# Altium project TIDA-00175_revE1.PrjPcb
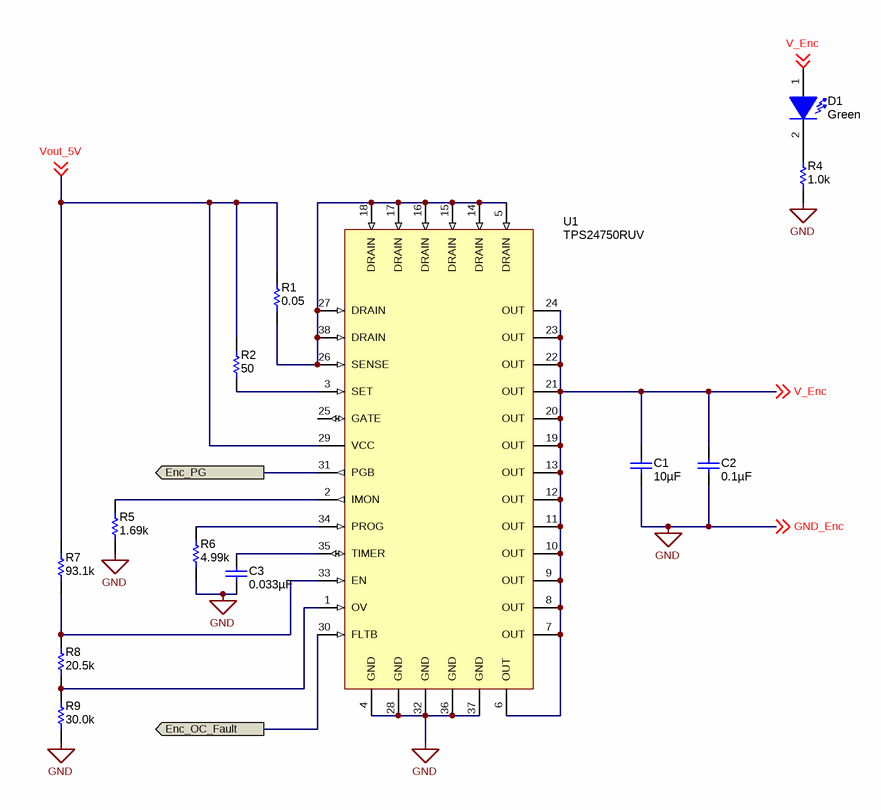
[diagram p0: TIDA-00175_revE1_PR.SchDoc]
CopyrightYear: 2014; PCB_Layout: Mogensen; PCB_Rev: E1; PRJ_Customer: Public Release; PRJ_Engineer: Mogensen/Staebler; PRJ_Number: TIDA-00175; PRJ_Title: Interface to an BiSS-C Position Encoder; SCH_Rev: E1; TechSupport: http://www.ti.com/support
4 sheets, 124 parts. Net scope: flat (ports and power ports of the same name join across sheets).
Board file: TIDA-00175_revE1_PCB.PcbDoc
Sheets:
  TIDA-00175_revE1_PR.SchDoc
  TIDA-00175_revE1_PS.SchDoc
  TIDA-00175_revE1_SC.SchDoc
  TIDA-00175_revE1_Block_Diagram.SchDoc

## Sheet TIDA-00175_revE1_PR.SchDoc
size 431 x 279 mm; Date: Not shown in title block; ApprovedBy: Not shown in title block; CheckedBy: Not shown in title block; Author: Not shown in title block; CompanyName: Not shown in title block; Engineer: Not shown in title block; Organization: Not shown in title block; Address1: Not shown in title block; Address2: Not shown in title block; Address3: Not shown in title block; Address4: Not shown in title block; DocumentNumber: 3; Revision: Use project parameter SCH_Rev; SheetNumber: 3; SheetTotal: 4; PageSetup: Record=PageOptions|CenterHorizontal=True|CenterVertical=True|PrintScale=0.62|XCorrection=1.00|YCorrection=1.00|PrintKind=0|BorderSize=5000000|LeftOffset=0|BottomOffset=0|Orientation=2|PaperLength=1000|PaperWidth=1000|Scale=100|PaperSource=15|PrintQuality=600|MediaType=1|DitherType=10|PaperKind=Letter|PrintScaleMode=1

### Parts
C1  ValueDisplayed: 10µF  [0805_HV]  (hidden comment: C2012X5R1E106K125AB)
C2  ValueDisplayed: 0.1µF  [0603]  (hidden comment: C1608X7R1E104K)
C3  ValueDisplayed: 0.033µF  [0603]  (hidden comment: GRM188R71H333KA61D)
D1  value Green  [LG L29K_GREEN]  (hidden comment: LG L29K-G2J1-24-Z)
R1  value 0.05  [0603]  (hidden comment: ERJ-L03KF50MV)
R2  value 50  [0603]  (hidden comment: CRCW060350R0FKEA)
R4  value 1.0k  [0603]  (hidden comment: CRCW06031K00JNEA)
R5  value 1.69k  [0603]  (hidden comment: CRCW06031K69FKEA)
R6  value 4.99k  [0603]  (hidden comment: CRCW06034K99FKEA)
R7  value 93.1k  [0603]  (hidden comment: CRCW060393K1FKEA)
R8  value 20.5k  [0603]  (hidden comment: CRCW060320K5FKEA)
R9  value 30.0k  [0603]  (hidden comment: RC0603FR-0730KL)
U1  TPS24750RUV  [RUV0036A]

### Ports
Enc_OC_Fault (out), Enc_PG (out)

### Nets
GND: C1.2 C2.2 C3.1 R4.1 R5.1 R6.1 R9.1 U1.4(GND) U1.28(GND) U1.32(GND) U1.36(GND) U1.37(GND) ; off-sheet GND_Enc  [also labelled GND_Enc]
Enc_OC_Fault: U1.30(FLTB) ; port Enc_OC_Fault
Enc_PG: U1.31(PGB) ; port Enc_PG
V_Enc: C1.1 C2.1 D1.1(A) U1.6(OUT) U1.7(OUT) U1.8(OUT) U1.9(OUT) U1.10(OUT) U1.11(OUT) U1.12(OUT) U1.13(OUT) U1.19(OUT) U1.20(OUT) U1.21(OUT) U1.22(OUT) U1.23(OUT) U1.24(OUT) ; off-sheet V_Enc
Vout_5V: R1.2 R2.2 R7.2 U1.29(VCC) ; off-sheet Vout_5V
NetC3_2: C3.2 U1.35(TIMER)
NetD1_2: D1.2(K) R4.2
NetR1_1: R1.1 U1.5(DRAIN) U1.14(DRAIN) U1.15(DRAIN) U1.16(DRAIN) U1.17(DRAIN) U1.18(DRAIN) U1.26(SENSE) U1.27(DRAIN) U1.38(DRAIN)
NetR2_1: R2.1 U1.3(SET)
NetR5_2: R5.2 U1.2(IMON)
NetR6_2: R6.2 U1.34(PROG)
NetR7_1: R7.1 R8.2 U1.33(EN)
NetR8_1: R8.1 R9.2 U1.1(OV)

Not connected (* = marked no-connect by the designer): U1 25(GATE)

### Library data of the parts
C1 = C2012X5R1E106K125AB: CAP, CERM, 10uF, 25V, +/-10%, X5R, 0805; Manufacturer: TDK; Polarized: N; CompType: Capacitor; U/M: EA; Cap_F: 0.00001; Tolerance_%: 10; Value1: Unknown; VDC_V: 25; TaMin_C: -55; TaMax_C: 85; Cap_Case: 0805
C2 = C1608X7R1E104K: CAP, CERM, 0.1uF, 25V, +/-10%, X7R, 0603; Manufacturer: TDK; Polarized: N; CompType: Capacitor; U/M: EA; Cap_F: 0.0000001; Tolerance_%: 10; ESR_Ohm: 0.017; Value1: 0.017 ohm; VDC_V: 25; TaMin_C: -55; TaMax_C: 125
C3 = GRM188R71H333KA61D: CAP, CERM, 0.033uF, 50V, +/-10%, X7R, 0603; Manufacturer: MuRata; Polarized: N; CompType: Capacitor; U/M: EA; Cap_F: 0.000000033; Tolerance_%: 10; Value1: Unknown; VDC_V: 50; TaMin_C: -55; TaMax_C: 125
D1 = LG L29K-G2J1-24-Z: LED, Green, SMD; Manufacturer: OSRAM; Vf_V: 1.7; Value2: 1.7V; Io_A: 0.002; Tjmax_C: 110; Value1: W; U/M: EA
R1 = ERJ-L03KF50MV: RES, 0.05 ohm, 1%, 0.1W, 0603; Manufacturer: Panasonic; CompType: Resistor; Value_Code: R050; Tolerance_%: 1; Power_W: 0.1; TempCo: 200 ppm/C; EIA_Code: E96; U/M: EA
R2 = CRCW060350R0FKEA: RES, 50 ohm, 1%, 0.1W, 0603; Manufacturer: Vishay-Dale; CompType: Resistor; Value_Code: 50R0; Tolerance_%: 1; Power_W: 0.1; VDC_V: 75; TempCo: 100 ppm/C; U/M: EA
R4 = CRCW06031K00JNEA: RES, 1.0k ohm, 5%, 0.1W, 0603; Manufacturer: Vishay-Dale; CompType: Resistor; Res_ohm: 1000; Value_Code: 1k00; Tolerance_%: 5; Power_W: 0.1; VDC_V: 75; TempCo: 200 ppm/C; EIA_Code: E24; U/M: EA
R5 = CRCW06031K69FKEA: RES, 1.69k ohm, 1%, 0.1W, 0603; Manufacturer: Vishay-Dale; CompType: Resistor; Res_ohm: 1690; Value_Code: 1k69; Tolerance_%: 1; Power_W: 0.1; VDC_V: 75; TempCo: 100 ppm/C; EIA_Code: E96; U/M: EA
R6 = CRCW06034K99FKEA: RES, 4.99k ohm, 1%, 0.1W, 0603; Manufacturer: Vishay-Dale; CompType: Resistor; Res_ohm: 4990; Value_Code: 4k99; Tolerance_%: 1; Power_W: 0.1; VDC_V: 75; TempCo: 100 ppm/C; EIA_Code: E96; U/M: EA
R7 = CRCW060393K1FKEA: RES, 93.1k ohm, 1%, 0.1W, 0603; Manufacturer: Vishay-Dale; CompType: Resistor; Res_ohm: 93100; Value_Code: 93k1; Tolerance_%: 1; Power_W: 0.1; VDC_V: 75; TempCo: 100 ppm/C; EIA_Code: E96; U/M: EA
R8 = CRCW060320K5FKEA: RES, 20.5k ohm, 1%, 0.1W, 0603; Manufacturer: Vishay-Dale; CompType: Resistor; Res_ohm: 20500; Value_Code: 20k5; Tolerance_%: 1; Power_W: 0.1; VDC_V: 75; TempCo: 100 ppm/C; EIA_Code: E96; U/M: EA
R9 = RC0603FR-0730KL: RES, 30.0k ohm, 1%, 0.1W, 0603; Manufacturer: Yageo America; CompType: Resistor; Res_ohm: 30000; Value_Code: 30k0; Tolerance_%: 1; Power_W: 0.1; VDC_V: 150; TempCo: 200 ppm/C; U/M: EA
U1 = TPS24750RUV: 2.5 to 18 V Positive Voltage 10A Integrated Hot-Swap Controller, RUV0036A; Alternate Manufacturer: None; Manufacturer: Texas Instruments; SymbolCreator: a0411947; CompType: IC; U/M: EA

## Sheet TIDA-00175_revE1_PS.SchDoc
size 431 x 279 mm; Date: Not shown in title block; ApprovedBy: Not shown in title block; CheckedBy: Not shown in title block; Author: Not shown in title block; CompanyName: Not shown in title block; Engineer: Not shown in title block; Organization: Not shown in title block; Address1: Not shown in title block; Address2: Not shown in title block; Address3: Not shown in title block; Address4: Not shown in title block; DocumentNumber: 2; Revision: Use project parameter SCH_Rev; SheetNumber: 2; SheetTotal: 4; PageSetup: Record=PageOptions|CenterHorizontal=True|CenterVertical=True|PrintScale=0.62|XCorrection=1.00|YCorrection=1.00|PrintKind=0|BorderSize=5000000|LeftOffset=0|BottomOffset=0|Orientation=2|PaperLength=1000|PaperWidth=1000|Scale=100|PaperSource=15|PrintQuality=600|MediaType=1|DitherType=10|PaperKind=Letter|PrintScaleMode=1
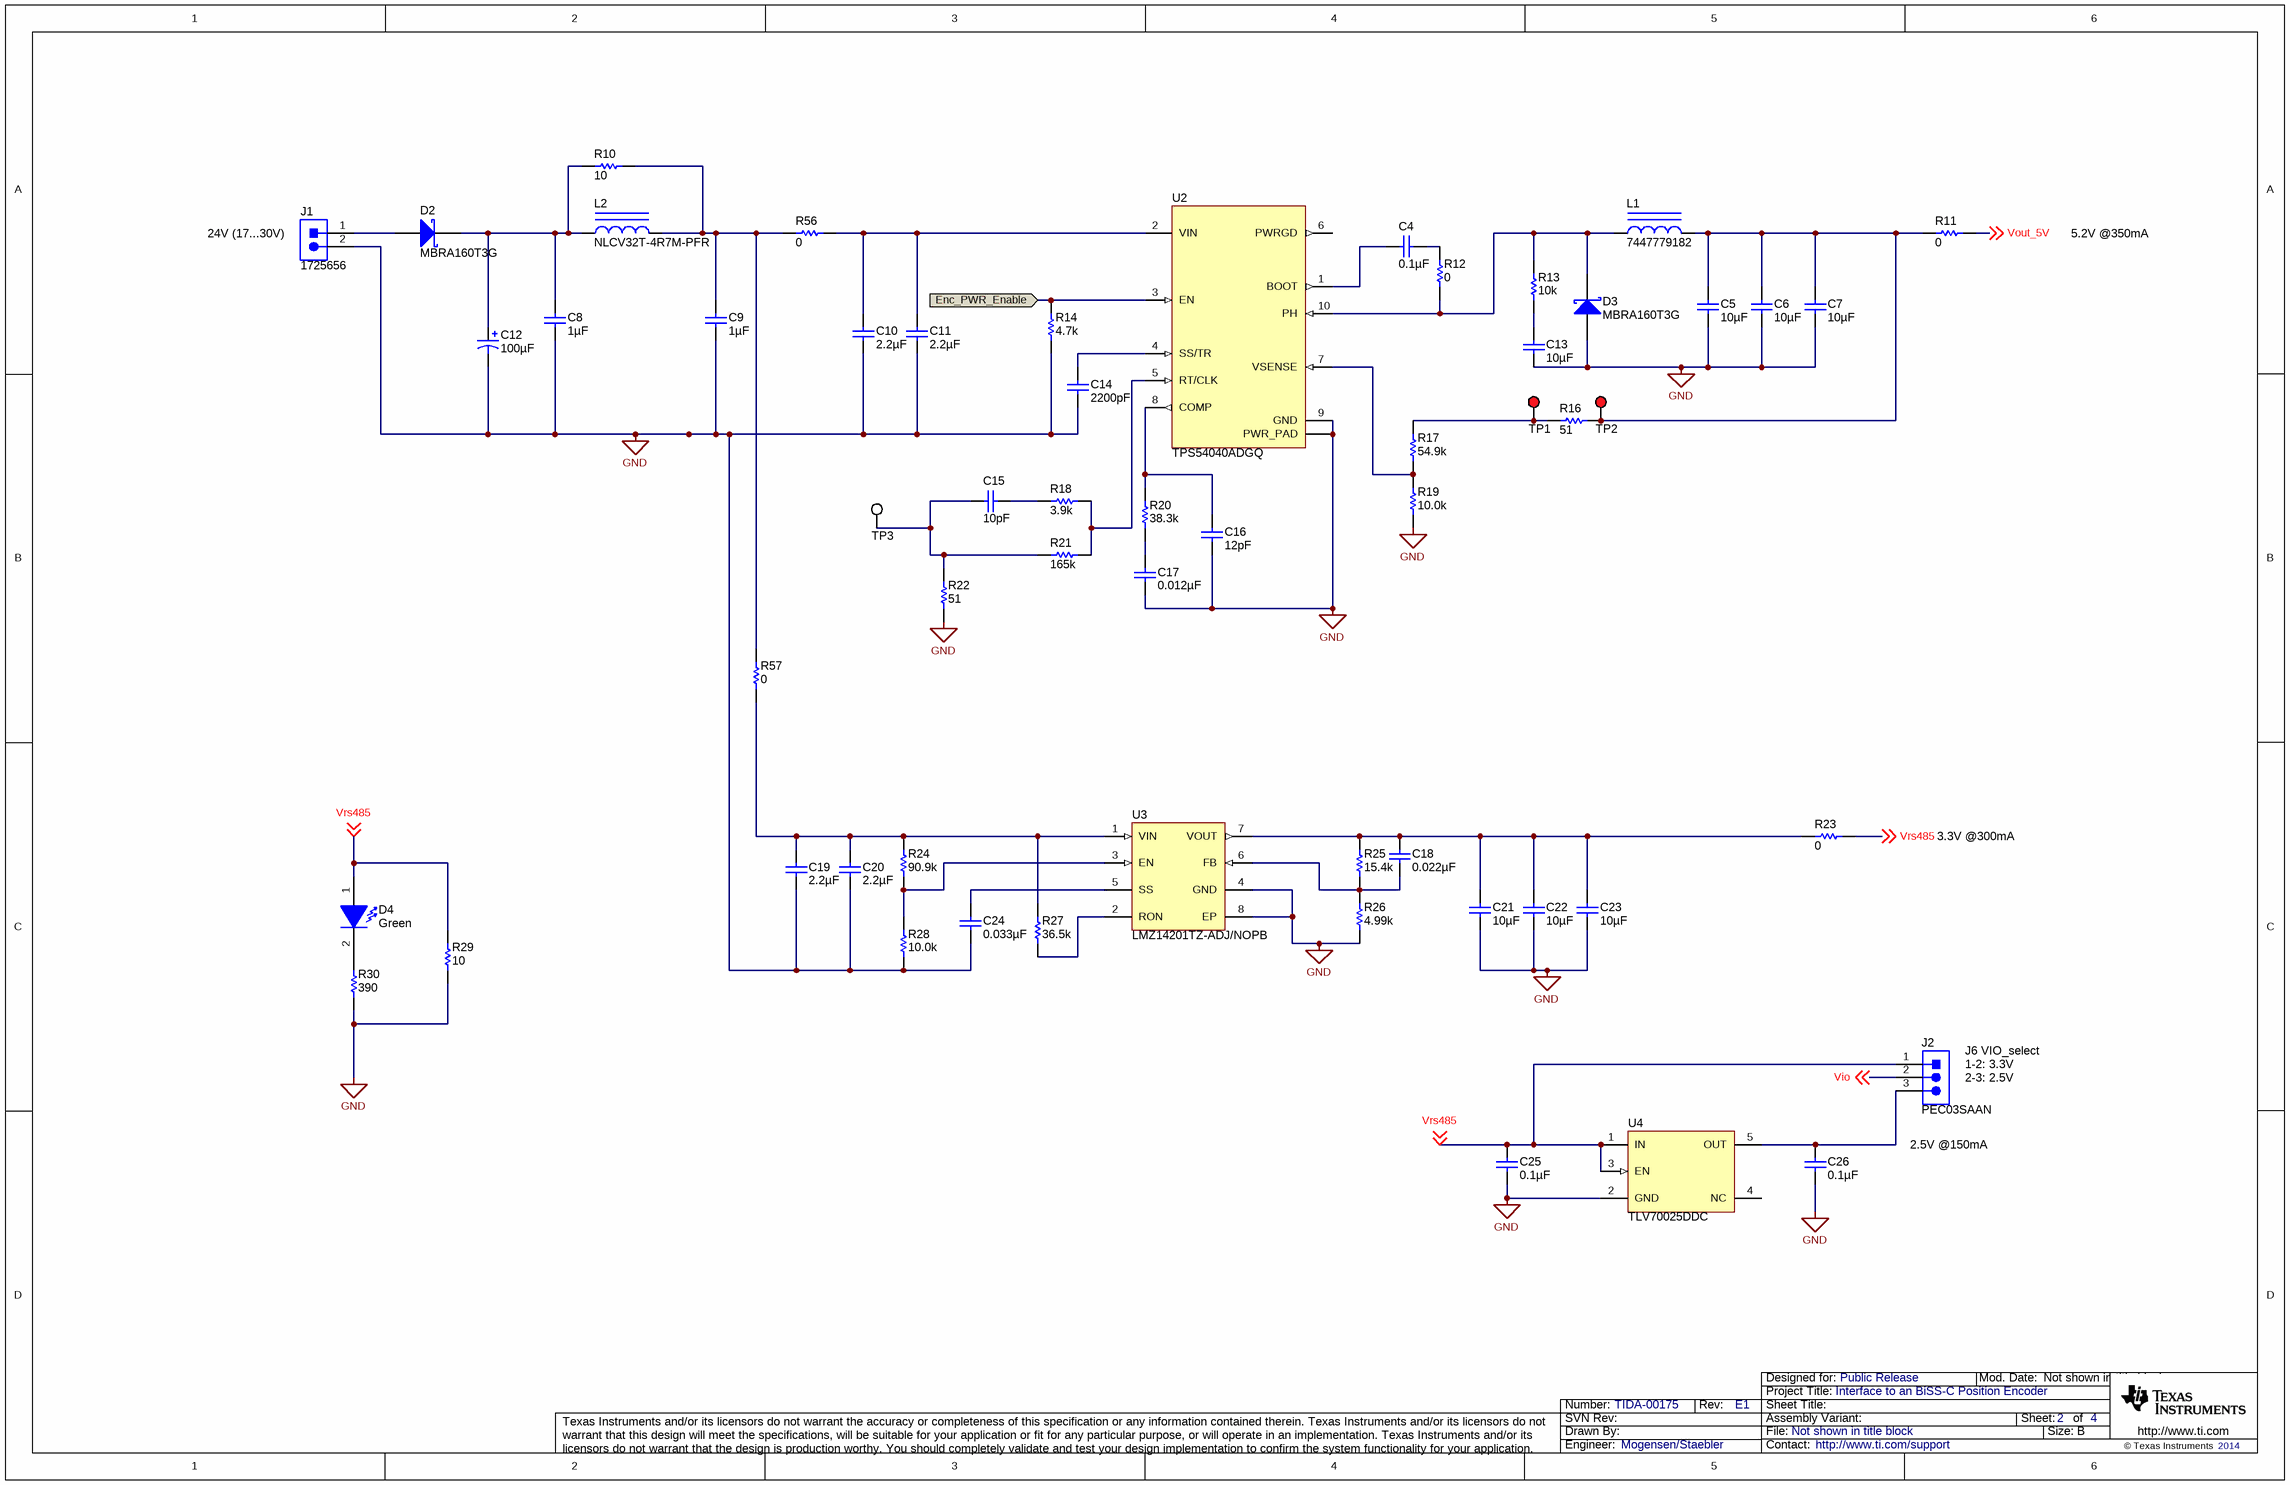
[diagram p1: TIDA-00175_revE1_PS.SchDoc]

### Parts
C4  ValueDisplayed: 0.1µF  [0603]  (hidden comment: GRM188R61C104KA01D)
C5  ValueDisplayed: 10µF  [0805_HV]  (hidden comment: C2012X5R1E106K125AB)
C6  ValueDisplayed: 10µF  [0805_HV]  (hidden comment: C2012X5R1E106K125AB)
C7  ValueDisplayed: 10µF  [0805_HV]  (hidden comment: C2012X5R1E106K125AB)
C8  ValueDisplayed: 1µF  [0805_HV]  (hidden comment: GRM21BR71H105KA12L)
C9  ValueDisplayed: 1µF  [0805_HV]  (hidden comment: GRM21BR71H105KA12L)
C10  ValueDisplayed: 2.2µF  [1206]  (hidden comment: GRM31CR61H225KA88L)
C11  ValueDisplayed: 2.2µF  [1206]  (hidden comment: GRM31CR61H225KA88L)
C12  ValueDisplayed: 100µF  [SM_RADIAL_G]  (hidden comment: EEE-FK1J101P)
C13  ValueDisplayed: 10µF  [0603]  (hidden comment: GRM188R60J106ME47D)
C14  ValueDisplayed: 2200pF  [0603]  (hidden comment: GRM188R71C222KA01D)
C15  ValueDisplayed: 10pF  [0603]  (hidden comment: C1608C0G1H100D)
C16  ValueDisplayed: 12pF  [0603]  (hidden comment: GRM1885C1H120JA01D)
C17  ValueDisplayed: 0.012µF  [0603_HV]  (hidden comment: GRM188R71H123KA01D)
C18  ValueDisplayed: 0.022µF  [0603]  (hidden comment: GRM188R71C223KA01D)
C19  ValueDisplayed: 2.2µF  [1206]  (hidden comment: GRM31CR61H225KA88L)
C20  ValueDisplayed: 2.2µF  [1206]  (hidden comment: GRM31CR61H225KA88L)
C21  ValueDisplayed: 10µF  [0603]  (hidden comment: C1608X5R1A106M)
C22  ValueDisplayed: 10µF  [0603]  (hidden comment: C1608X5R1A106M)
C23  ValueDisplayed: 10µF  [0603]  (hidden comment: C1608X5R1A106M)
C24  ValueDisplayed: 0.033µF  [0603]  (hidden comment: GRM188R71C333KA01D)
C25  ValueDisplayed: 0.1µF  [0603]  (hidden comment: GRM188R61C104KA01D)
C26  ValueDisplayed: 0.1µF  [0603]  (hidden comment: GRM188R61C104KA01D)
D2  MBRA160T3G  [SMA]
D3  MBRA160T3G  [SMA]
D4  value Green  [LG L29K_GREEN]  (hidden comment: LG L29K-G2J1-24-Z)
J1  1725656  [CONN_1725656]
J2  PEC03SAAN  [CONN_PEC03SAAN]
L1  7447779182  [WE-PD-M]
L2  NLCV32T-4R7M-PFR  [NLCV32]
R10  value 10  [0603]  (hidden comment: CRCW060310R0JNEAHP)
R11  value 0  [0603]  (hidden comment: CRCW06030000Z0EA)
R12  value 0  [0603]  (hidden comment: CRCW06030000Z0EA)
R13  value 10k  [0805_HV]  (hidden comment: CRCW080510K0JNEA)
R14  value 4.7k  [0603]  (hidden comment: CRCW06034K70JNEA)
R16  value 51  [0603]  (hidden comment: CRCW060351R0JNEA)
R17  value 54.9k  [0603]  (hidden comment: CRCW060354K9FKEA)
R18  value 3.9k  [0603]  (hidden comment: CRCW06033K90JNEA)
R19  value 10.0k  [0603]  (hidden comment: CRCW060310K0FKEA)
R20  value 38.3k  [0603]  (hidden comment: CRCW060338K3FKEA)
R21  value 165k  [0603]  (hidden comment: CRCW0603165KFKEA)
R22  value 51  [0603]  (hidden comment: CRCW060351R0JNEA)
R23  value 0  [0603]  (hidden comment: CRCW06030000Z0EA)
R24  value 90.9k  [0603]  (hidden comment: CRCW060390K9FKEA)
R25  value 15.4k  [0603]  (hidden comment: CRCW060315K4FKEA)
R26  value 4.99k  [0603_HV]  (hidden comment: CRCW06034K99FKEA)
R27  value 36.5k  [0603]  (hidden comment: CRCW060336K5FKEA)
R28  value 10.0k  [0603]  (hidden comment: CRCW060310K0FKEA)
R29  value 10  [RESAD2032W80L1300D480]  (hidden comment: AC03000001009JAC00)
R30  value 390  [0603]  (hidden comment: CRCW0603390RJNEA)
R56  value 0  [0603]  (hidden comment: CRCW06030000Z0EA)
R57  value 0  [0603]  (hidden comment: CRCW06030000Z0EA)
TP1  5000  [Keystone5000]  (value not drawn)
TP2  5000  [Keystone5000]  (value not drawn)
TP3  5002  [Keystone5002]  (value not drawn)
U2  TPS54040ADGQ  [DGQ0010D_N]
U3  LMZ14201TZ-ADJ/NOPB  [TZA07A_V]
U4  TLV70025DDC  [DDC0005A_N]

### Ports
Enc_PWR_Enable (in)

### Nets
GND: C5.2 C6.2 C7.2 C8.2 C9.2 C10.2 C11.2 C12.2(-) C13.2 C14.2 C16.2 C17.2 C19.2 C20.2 C21.2 C22.2 C23.2 C24.2 C25.2 C26.2 D3.2(A) J1.2 R14.2 R19.1 R22.1 R26.1 R28.1 R29.1 R30.1 U2.9(GND) U2.11(PWR_PAD) U3.4(GND) U3.8(EP) U4.2(GND)
Enc_PWR_Enable: R14.1 U2.3(EN) ; port Enc_PWR_Enable
Vio: J2.2 ; off-sheet Vio
Vout_5V: R11.2 ; off-sheet Vout_5V
Vrs485: C25.1 D4.1(A) J2.1 R23.2 R29.2 U4.1(IN) U4.3(EN) ; off-sheet Vrs485
NetC4_1: C4.1 U2.1(BOOT)
NetC4_2: C4.2 R12.1
NetC5_1: C5.1 C6.1 C7.1 L1.2 R11.1 R16.1 TP2.1
NetC8_1: C8.1 C12.1(+) D2.1(K) L2.1 R10.1
NetC9_1: C9.1 L2.2 R10.2 R56.1 R57.2
NetC10_1: C10.1 C11.1 R56.2 U2.2(VIN)
NetC13_1: C13.1 R13.1
NetC14_1: C14.1 U2.4(SS/TR)
NetC15_1: C15.1 R18.1
NetC15_2: C15.2 R21.1 R22.2 TP3.1
NetC16_1: C16.1 R20.2 U2.8(COMP)
NetC17_1: C17.1 R20.1
NetC18_1: C18.1 C21.1 C22.1 C23.1 R23.1 R25.2 U3.7(VOUT)
NetC18_2: C18.2 R25.1 R26.2 U3.6(FB)
NetC19_1: C19.1 C20.1 R24.2 R27.1 R57.1 U3.1(VIN)
NetC24_1: C24.1 U3.5(SS)
NetC26_1: C26.1 J2.3 U4.5(OUT)
NetD2_2: D2.2(A) J1.1
NetD3_1: D3.1(K) L1.1 R12.2 R13.2 U2.10(PH)
NetD4_2: D4.2(K) R30.2
NetR16_2: R16.2 R17.2 TP1.1
NetR17_1: R17.1 R19.2 U2.7(VSENSE)
NetR18_2: R18.2 R21.2 U2.5(RT/CLK)
NetR24_1: R24.1 R28.2 U3.3(EN)
NetR27_2: R27.2 U3.2(RON)

Not connected (* = marked no-connect by the designer): U2 6(PWRGD); U4 4(NC)

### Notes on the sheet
- (near J1) 24V (17...30V)
- 5.2V @350mA
- 3.3V @300mA
- (near J2) 1-2: 3.3V
- (near J2) 2-3: 2.5V
- (near J2) J6 VIO_select
- (near J2) 2.5V @150mA

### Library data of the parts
C4 C25 C26 = GRM188R61C104KA01D: CAP, CERM, 0.1uF, 16V, +/-10%, X5R, 0603; Manufacturer: MuRata; Polarized: N; CompType: Capacitor; U/M: EA; Cap_F: 0.0000001; Tolerance_%: 10; Value1: Unknown; VDC_V: 16; TaMin_C: -55; TaMax_C: 85
C5-C7 = C2012X5R1E106K125AB: as C1 on sheet TIDA-00175_revE1_PR
C8 C9 = GRM21BR71H105KA12L: CAP, CERM, 1uF, 50V, +/-10%, X7R, 0805; Manufacturer: MuRata; Polarized: N; CompType: Capacitor; U/M: EA; Cap_F: 0.000001; Tolerance_%: 10; Value1: Unknown; VDC_V: 50; TaMin_C: -55; TaMax_C: 125; Cap_Case: 0805
C10 C11 C19 C20 = GRM31CR61H225KA88L: CAP, CERM, 2.2uF, 50V, +/-10%, X5R, 1206; Manufacturer: MuRata; Polarized: N; CompType: Capacitor; U/M: EA; Cap_F: 0.0000022; Tolerance_%: 10; Value1: Unknown; VDC_V: 50; TaMin_C: -55; TaMax_C: 85
C12 = EEE-FK1J101P: CAP, AL, 100uF, 63V, +/-20%, 0.35 ohm, SMD; Manufacturer: Panasonic; Polarized: Y; CompType: Capacitor; U/M: EA; Cap_F: 0.0001; Tolerance_%: 20; VDC_V: 63; ESR_Ohm: 0.35; IRMS_A: 0.4; TaMin_C: -55; TaMax_C: 105; Cap_Case: G
C13 = GRM188R60J106ME47D: CAP, CERM, 10uF, 6.3V, +/-20%, X5R, 0603; Manufacturer: MuRata; Polarized: N; CompType: Capacitor; U/M: EA; Cap_F: 0.00001; Tolerance_%: 20; ESR_Ohm: 0.009; Value1: 0.009 ohm; VDC_V: 6.3; IRMS_A: 2.74; TaMin_C: -55; TaMax_C: 125
C14 = GRM188R71C222KA01D: CAP, CERM, 2200pF, 16V, +/-10%, X7R, 0603; Manufacturer: MuRata; Polarized: N; CompType: Capacitor; U/M: EA; Cap_F: 0.0000000022; Tolerance_%: 10; Value1: Unknown; VDC_V: 16; TaMin_C: -55; TaMax_C: 125
C15 = C1608C0G1H100D: CAP, CERM, 10pF, 50V, +/-5%, C0G/NP0, 0603; Manufacturer: TDK; Polarized: N; CompType: Capacitor; U/M: EA; Cap_F: 0.00000000001; Tolerance_%: 5; ESR_Ohm: 0.3492; Value1: 0.3492 ohm; VDC_V: 50; TaMin_C: -55; TaMax_C: 125
C16 = GRM1885C1H120JA01D: CAP, CERM, 12pF, 50V, +/-5%, C0G/NP0, 0603; Manufacturer: MuRata; Polarized: N; CompType: Capacitor; U/M: EA; Cap_F: 0.000000000012; Tolerance_%: 5; Value1: Unknown; VDC_V: 50; TaMin_C: -55; TaMax_C: 125
C17 = GRM188R71H123KA01D: CAP, CERM, 0.012uF, 50V, +/-10%, X7R, 0603; Manufacturer: MuRata; Polarized: N; CompType: Capacitor; U/M: EA; Cap_F: 0.000000012; Tolerance_%: 10; Value1: Unknown; VDC_V: 50; TaMin_C: -55; TaMax_C: 125; Cap_Case: 0603
C18 = GRM188R71C223KA01D: CAP, CERM, 0.022uF, 16V, +/-10%, X7R, 0603; Manufacturer: MuRata; Polarized: N; CompType: Capacitor; U/M: EA; Cap_F: 0.000000022; Tolerance_%: 10; Value1: Unknown; VDC_V: 16; TaMin_C: -55; TaMax_C: 125
C21-C23 = C1608X5R1A106M: CAP, CERM, 10uF, 10V, +/-20%, X5R, 0603; Manufacturer: TDK; Polarized: N; CompType: Capacitor; U/M: EA; Cap_F: 0.00001; Tolerance_%: 20; ESR_Ohm: 0.0078; Value1: 0.0078 ohm; VDC_V: 10; IRMS_A: 1.85; TaMin_C: -55; TaMax_C: 85
C24 = GRM188R71C333KA01D: CAP, CERM, 0.033uF, 16V, +/-10%, X7R, 0603; Manufacturer: MuRata; Polarized: N; CompType: Capacitor; U/M: EA; Cap_F: 0.000000033; Tolerance_%: 10; Value1: Unknown; VDC_V: 16; TaMin_C: -55; TaMax_C: 125
D2 D3 = MBRA160T3G: Diode, Schottky, 60V, 1A, SMA; Manufacturer: ON Semiconductor; U/M: EA; Vf_V: 0.51; Value2: 0.51V; Io_A: 1; Vr_V: 60; TJmax_C: 150; RJC_CperW: 35
D4 = LG L29K-G2J1-24-Z: as D1 on sheet TIDA-00175_revE1_PR
J1 = 1725656: Header, 2 Pos, 6A, 63V, TH; Manufacturer: Phoenix Contact; SymbolCreator: a0412235; U/M: EA
J2 = PEC03SAAN: Header, 100mil, 3x1, Tin plated, TH; Manufacturer: Sullins Connector Solutions; SymbolCreator: a0799628; U/M: EA
L1 = 7447779182: Inductor, Shielded Drum Core, Ferrite, 82uH, 0.84A, 0.25 ohm, SMD; Manufacturer: Wurth Elektronik eiSos; Ind_H: 82.0E-6; ValueDisplayed: 82µH; Imax_A: 0.84; Irms: 0.84A @ 40C rise; Isat: 0.9A @ 10% inductance drop; DCR_ohm: 0.25
L2 = NLCV32T-4R7M-PFR: Inductor, Wirewound, Ferrite, 4.7uH, 0.9A, 0.2 ohm, SMD; Manufacturer: TDK; Ind_H: 4.7E-6; ValueDisplayed: 4.7µH; Imax_A: 0.9; Irms: 0.9A @ 20C rise; Isat: 0.9A @ 10% inductance drop; DCR_ohm: 0.2; Value1: 0.2 ohm; U/M: EA
R10 = CRCW060310R0JNEAHP: RES, 10 ohm, 5%, 0.25W, 0603; Manufacturer: Vishay-Dale; CompType: Resistor; Value_Code: 10R0; Tolerance_%: 5; Power_W: 0.25; VDC_V: 75; TempCo: 200 ppm/C; EIA_Code: E24; U/M: EA
R11 R12 R23 R56 R57 = CRCW06030000Z0EA: RES, 0 ohm, 5%, 0.1W, 0603; Manufacturer: Vishay-Dale; CompType: Resistor; Value_Code: 0000; Tolerance_%: 5; Power_W: 0.1; VDC_V: 75; TempCo: 200 ppm/C; EIA_Code: E24; U/M: EA
R13 = CRCW080510K0JNEA: RES, 10k ohm, 5%, 0.125W, 0805; Manufacturer: Vishay-Dale; CompType: Resistor; Res_ohm: 10000; Value_Code: 10k0; Tolerance_%: 5; Power_W: 0.125; VDC_V: 150; TempCo: 200 ppm/C; EIA_Code: E24; U/M: EA
R14 = CRCW06034K70JNEA: RES, 4.7k ohm, 5%, 0.1W, 0603; Manufacturer: Vishay-Dale; CompType: Resistor; Res_ohm: 4700; Value_Code: 4k70; Tolerance_%: 5; Power_W: 0.1; VDC_V: 75; TempCo: 200 ppm/C; EIA_Code: E24; U/M: EA
R16 R22 = CRCW060351R0JNEA: RES, 51 ohm, 5%, 0.1W, 0603; Manufacturer: Vishay-Dale; CompType: Resistor; Value_Code: 51R0; Tolerance_%: 5; Power_W: 0.1; VDC_V: 75; TempCo: 200 ppm/C; EIA_Code: E24; U/M: EA
R17 = CRCW060354K9FKEA: RES, 54.9k ohm, 1%, 0.1W, 0603; Manufacturer: Vishay-Dale; CompType: Resistor; Res_ohm: 54900; Value_Code: 54k9; Tolerance_%: 1; Power_W: 0.1; VDC_V: 75; TempCo: 100 ppm/C; EIA_Code: E96; U/M: EA
R18 = CRCW06033K90JNEA: RES, 3.9k ohm, 5%, 0.1W, 0603; Manufacturer: Vishay-Dale; CompType: Resistor; Res_ohm: 3900; Value_Code: 3k90; Tolerance_%: 5; Power_W: 0.1; VDC_V: 75; TempCo: 200 ppm/C; EIA_Code: E24; U/M: EA
R19 R28 = CRCW060310K0FKEA: RES, 10.0k ohm, 1%, 0.1W, 0603; Manufacturer: Vishay-Dale; CompType: Resistor; Res_ohm: 10000; Value_Code: 10k0; Tolerance_%: 1; Power_W: 0.1; VDC_V: 75; TempCo: 100 ppm/C; EIA_Code: E96; U/M: EA
R20 = CRCW060338K3FKEA: RES, 38.3k ohm, 1%, 0.1W, 0603; Manufacturer: Vishay-Dale; CompType: Resistor; Res_ohm: 38300; Value_Code: 38k3; Tolerance_%: 1; Power_W: 0.1; VDC_V: 75; TempCo: 100 ppm/C; EIA_Code: E96; U/M: EA
R21 = CRCW0603165KFKEA: RES, 165k ohm, 1%, 0.1W, 0603; Manufacturer: Vishay-Dale; CompType: Resistor; Res_ohm: 165000; Tolerance_%: 1; Power_W: 0.1; VDC_V: 75; TempCo: 100 ppm/C; EIA_Code: E96; U/M: EA
R24 = CRCW060390K9FKEA: RES, 90.9k ohm, 1%, 0.1W, 0603; Manufacturer: Vishay-Dale; CompType: Resistor; Res_ohm: 90900; Value_Code: 90k9; Tolerance_%: 1; Power_W: 0.1; VDC_V: 75; TempCo: 100 ppm/C; EIA_Code: E96; U/M: EA
R25 = CRCW060315K4FKEA: RES, 15.4k ohm, 1%, 0.1W, 0603; Manufacturer: Vishay-Dale; CompType: Resistor; Res_ohm: 15400; Value_Code: 15k4; Tolerance_%: 1; Power_W: 0.1; VDC_V: 75; TempCo: 100 ppm/C; EIA_Code: E96; U/M: EA
R26 = CRCW06034K99FKEA: as R6 on sheet TIDA-00175_revE1_PR
R27 = CRCW060336K5FKEA: RES, 36.5k ohm, 1%, 0.1W, 0603; Manufacturer: Vishay-Dale; CompType: Resistor; Res_ohm: 36500; Value_Code: 36k5; Tolerance_%: 1; Power_W: 0.1; VDC_V: 75; TempCo: 100 ppm/C; EIA_Code: E96; U/M: EA
R29 = AC03000001009JAC00: RES, 10 ohm, 5%, 3W, TH; Manufacturer: Vishay Draloric; CompType: Resistor; Value_Code: 10R0; Tolerance_%: 5; Power_W: 3; TempCo: 80 ppm/C; EIA_Code: E24; U/M: EA
R30 = CRCW0603390RJNEA: RES, 390 ohm, 5%, 0.1W, 0603; Manufacturer: Vishay-Dale; CompType: Resistor; Value_Code: 390R; Tolerance_%: 5; Power_W: 0.1; VDC_V: 75; TempCo: 200 ppm/C; EIA_Code: E24; U/M: EA
TP1 TP2 = 5000: Test Point, Miniature, Red, TH; Manufacturer: Keystone; CompType: Test Point Loop; U/M: EA
TP3 = 5002: Test Point, Miniature, White, TH; Manufacturer: Keystone; CompType: Test Point Loop; U/M: EA
U2 = TPS54040ADGQ: 0.5 A, 42 V Step Down DC/DC Converter with Eco-mode, DGQ0010D; Alternate Manufacturer: None; Manufacturer: Texas Instruments; SymbolCreator: a0411947; CompType: IC; U/M: EA
U3 = LMZ14201TZ-ADJ/NOPB: 1A SIMPLE SWITCHER® Power Module with 42V Maximum Input, 7 pin TO-PMOD; Manufacturer: National Semiconductor; PackageTopMarking: NSUZXYTTE#*LMZ14201*TZ-ADJ; PowerWise: Y
U4 = TLV70025DDC: 200-mA, Low-IQ, LDO Regulator for Portable Devices, DDC0005A; Alternate Manufacturer: None; Manufacturer: Texas Instruments; SymbolCreator: a0411947; CompType: IC; U/M: EA

## Sheet TIDA-00175_revE1_SC.SchDoc
size 431 x 279 mm; Date: Not shown in title block; ApprovedBy: Not shown in title block; CheckedBy: Not shown in title block; Author: Not shown in title block; CompanyName: Not shown in title block; Engineer: Not shown in title block; Organization: Not shown in title block; Address1: Not shown in title block; Address2: Not shown in title block; Address3: Not shown in title block; Address4: Not shown in title block; DocumentNumber: 4; Revision: Use project parameter SCH_Rev; SheetNumber: 4; SheetTotal: 4; PageSetup: Record=PageOptions|CenterHorizontal=True|CenterVertical=True|PrintScale=0.62|XCorrection=1.00|YCorrection=1.00|PrintKind=0|BorderSize=5000000|LeftOffset=0|BottomOffset=0|Orientation=2|PaperLength=1000|PaperWidth=1000|Scale=100|PaperSource=15|PrintQuality=600|MediaType=1|DitherType=10|PaperKind=Letter|PrintScaleMode=1
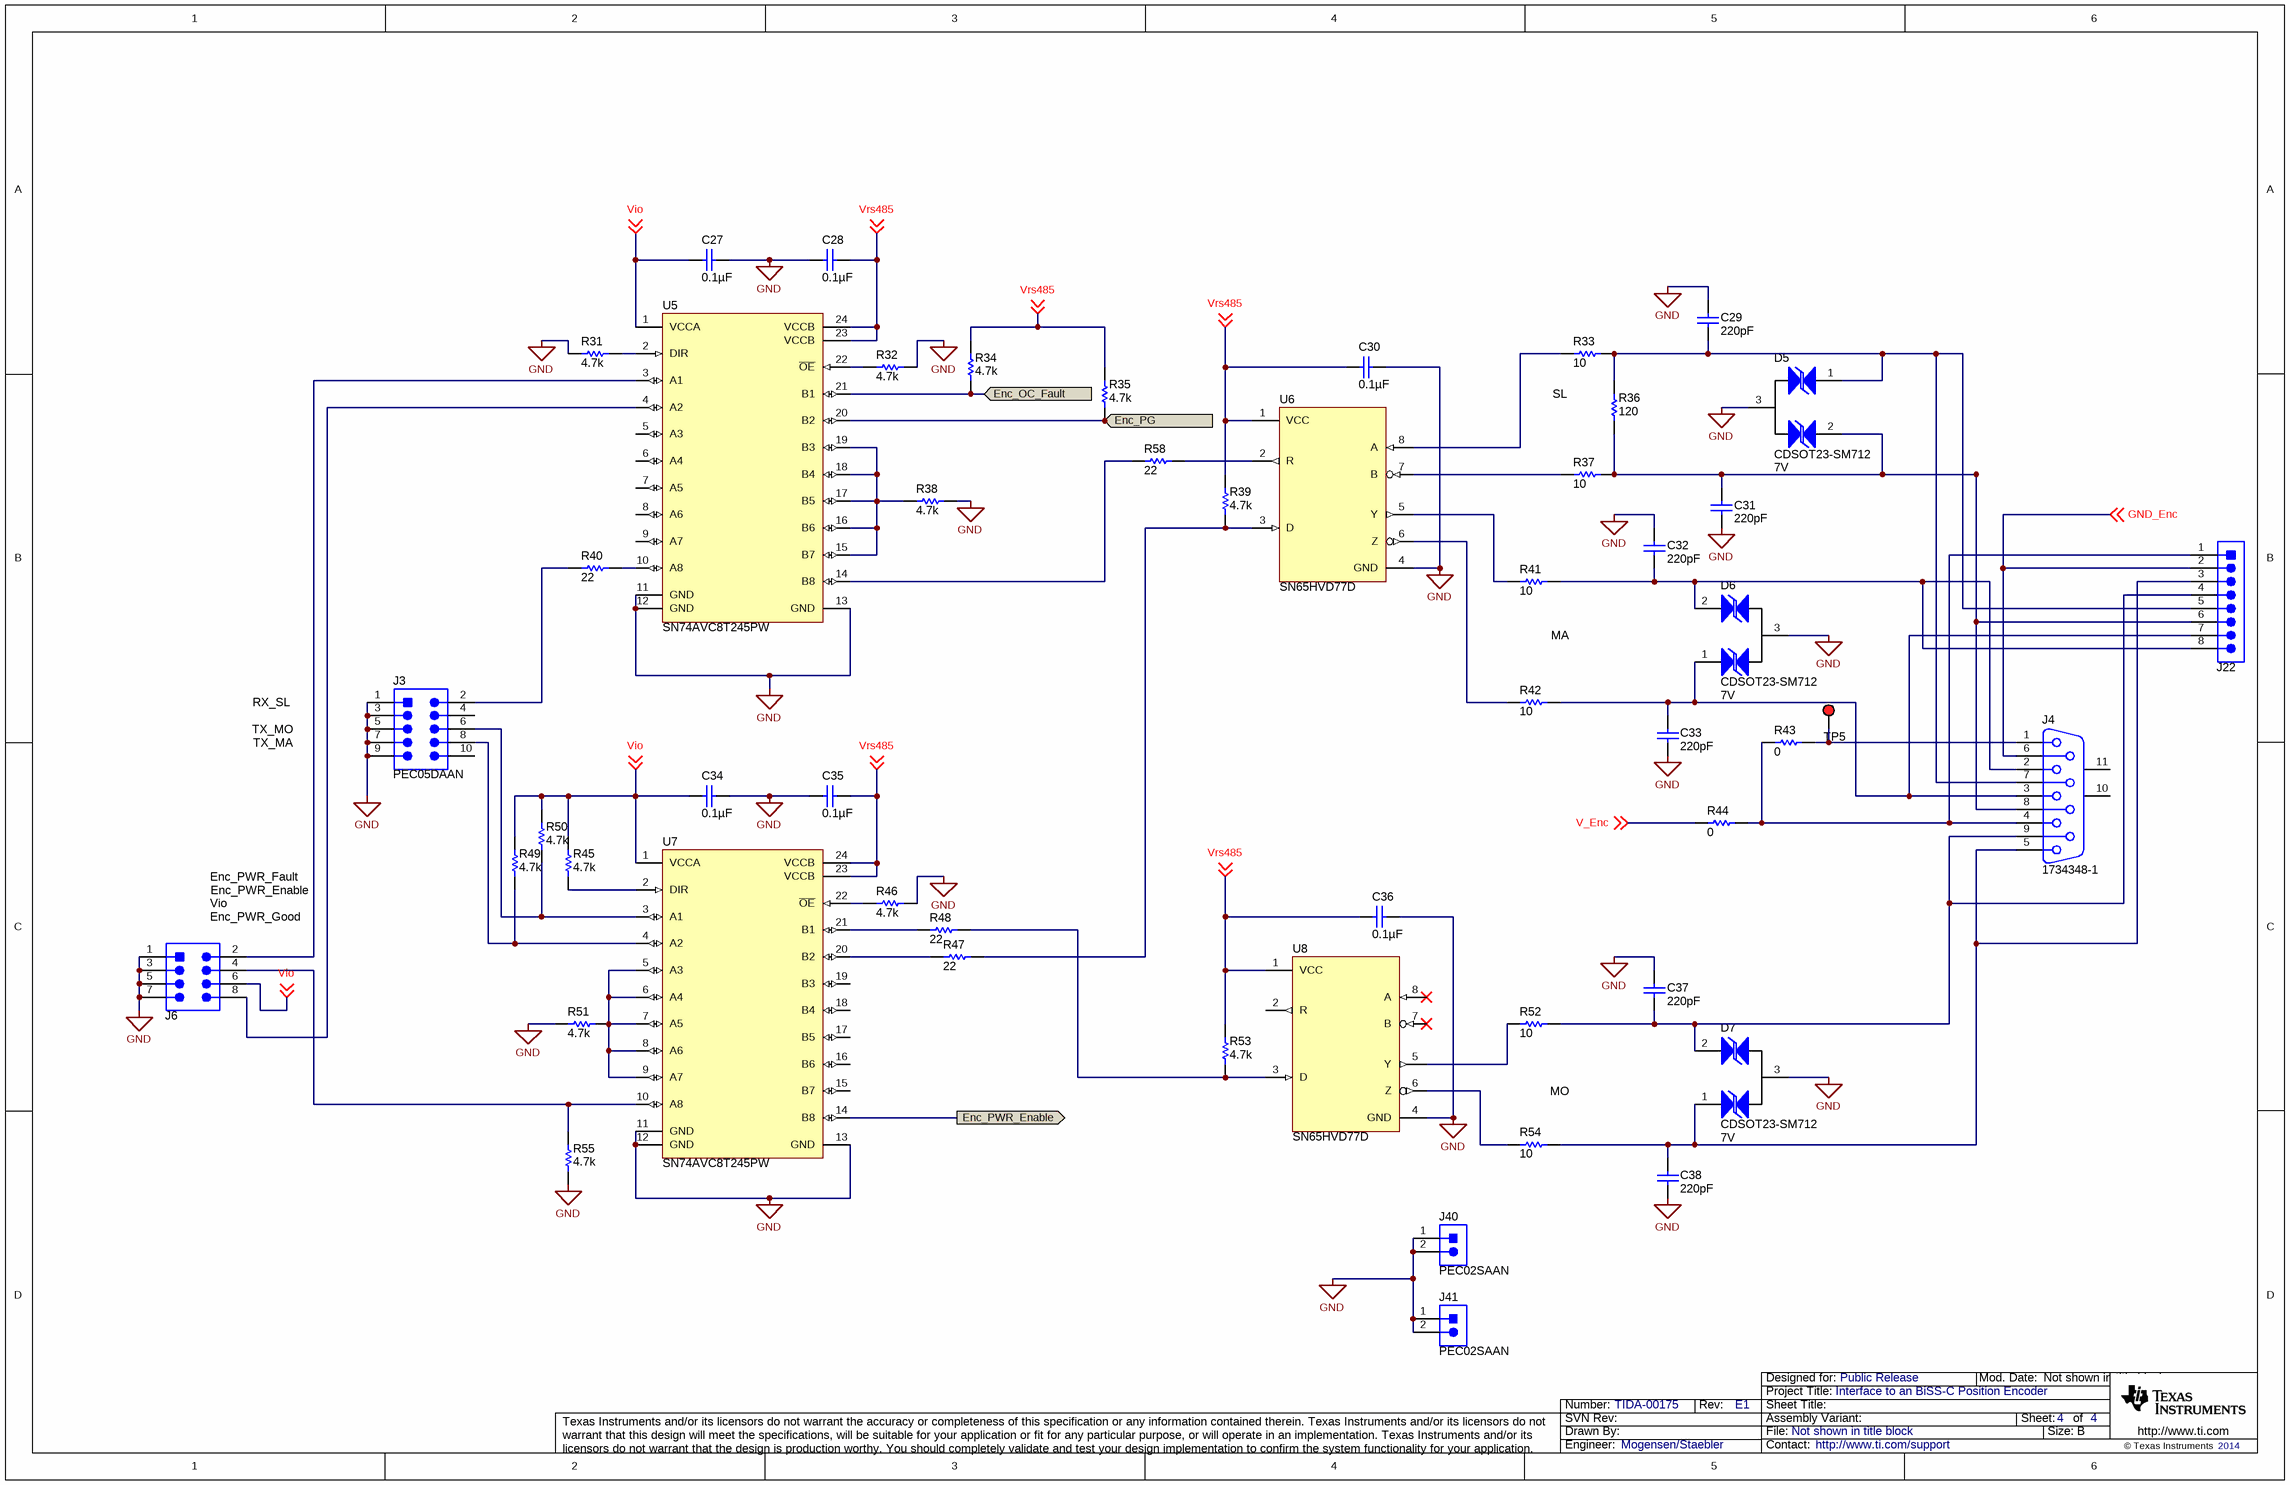
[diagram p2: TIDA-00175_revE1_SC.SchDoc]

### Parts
C27  ValueDisplayed: 0.1µF  [0603]  (hidden comment: 06033D104KAT2A)
C28  ValueDisplayed: 0.1µF  [0603]  (hidden comment: 06033D104KAT2A)
C29  ValueDisplayed: 220pF  [0603]  (hidden comment: GRM188R71H221KA01D)
C30  ValueDisplayed: 0.1µF  [0603]  (hidden comment: 06033D104KAT2A)
C31  ValueDisplayed: 220pF  [0603]  (hidden comment: GRM188R71H221KA01D)
C32  ValueDisplayed: 220pF  [0603]  (hidden comment: GRM188R71H221KA01D)
C33  ValueDisplayed: 220pF  [0603]  (hidden comment: GRM188R71H221KA01D)
C34  ValueDisplayed: 0.1µF  [0603]  (hidden comment: 06033D104KAT2A)
C35  ValueDisplayed: 0.1µF  [0603]  (hidden comment: 06033D104KAT2A)
C36  ValueDisplayed: 0.1µF  [0603]  (hidden comment: 06033D104KAT2A)
C37  ValueDisplayed: 220pF  [0603]  (hidden comment: GRM188R71H221KA01D)
C38  ValueDisplayed: 220pF  [0603]  (hidden comment: GRM188R71H221KA01D)
D5  CDSOT23-SM712  value 7V  [SOT-23]
D6  CDSOT23-SM712  value 7V  [SOT-23]
D7  CDSOT23-SM712  value 7V  [SOT-23]
J3  PEC05DAAN  [CONN_PEC05DAAN]
J4  1734348-1  [CONN_1734348-1]
J6  PEC04DAAN  [CONN_PEC04DAAN]  (value not drawn)
J22  PEC08SAAN  [SULLINS_PEC08SAAN]  (value not drawn)
J40  PEC02SAAN  [CONN_PEC02SAAN]
J41  PEC02SAAN  [CONN_PEC02SAAN]
R31  value 4.7k  [0603]  (hidden comment: CRCW06034K70JNEA)
R32  value 4.7k  [0603]  (hidden comment: CRCW06034K70JNEA)
R33  value 10  [0603]  (hidden comment: CRCW060310R0JNEAHP)
R34  value 4.7k  [0603_HV]  (hidden comment: CRCW06034K70JNEA)
R35  value 4.7k  [0603]  (hidden comment: CRCW06034K70JNEA)
R36  value 120  [0805_HV]  (hidden comment: ERJ-P06J121V)
R37  value 10  [0603]  (hidden comment: CRCW060310R0JNEAHP)
R38  value 4.7k  [0603]  (hidden comment: CRCW06034K70JNEA)
R39  value 4.7k  [0603_HV]  (hidden comment: CRCW06034K70JNEA)
R40  value 22  [0603]  (hidden comment: CRCW060322R0JNEA)
R41  value 10  [0603]  (hidden comment: CRCW060310R0JNEAHP)
R42  value 10  [0603]  (hidden comment: CRCW060310R0JNEAHP)
R43  value 0  [0603]  (hidden comment: CRCW06030000Z0EA)
R44  value 0  [0603]  (hidden comment: CRCW06030000Z0EA)
R45  value 4.7k  [0603]  (hidden comment: CRCW06034K70JNEA)
R46  value 4.7k  [0603]  (hidden comment: CRCW06034K70JNEA)
R47  value 22  [0603]  (hidden comment: CRCW060322R0JNEA)
R48  value 22  [0603]  (hidden comment: CRCW060322R0JNEA)
R49  value 4.7k  [0603]  (hidden comment: CRCW06034K70JNEA)
R50  value 4.7k  [0603]  (hidden comment: CRCW06034K70JNEA)
R51  value 4.7k  [0603]  (hidden comment: CRCW06034K70JNEA)
R52  value 10  [0603]  (hidden comment: CRCW060310R0JNEAHP)
R53  value 4.7k  [0603]  (hidden comment: CRCW06034K70JNEA)
R54  value 10  [0603]  (hidden comment: CRCW060310R0JNEAHP)
R55  value 4.7k  [0603]  (hidden comment: CRCW06034K70JNEA)
R58  value 22  [0603]  (hidden comment: CRCW060322R0JNEA)
TP5  5000  [Keystone5000]  (value not drawn)
U5  SN74AVC8T245PW  [PW0024A_N]
U6  SN65HVD77D  [D0008A_N]
U7  SN74AVC8T245PW  [PW0024A_N]
U8  SN65HVD77D  [D0008A_N]

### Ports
Enc_OC_Fault (in), Enc_PG (in), Enc_PWR_Enable (out)

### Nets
GND: C27.1 C28.2 C29.1 C30.1 C31.2 C32.1 C33.2 C34.1 C35.2 C36.1 C37.1 C38.2 D5.3 D6.3 D7.3 J3.1 J3.3 J3.5 J3.7 J3.9 J4.6 J6.1 J6.3 J6.5 J6.7 J22.2 J40.1 J40.2 J41.1 J41.2 R31.1 R32.2 R38.1 R46.1 R51.2 R55.1 U5.11(GND) U5.12(GND) U5.13(GND) U6.4(GND) U7.11(GND) U7.12(GND) U7.13(GND) U8.4(GND) ; off-sheet GND_Enc  [also labelled GND_Enc]
Enc_OC_Fault: R34.2 U5.21(B1) ; port Enc_OC_Fault
Enc_PG: R35.1 U5.20(B2) ; port Enc_PG
Enc_PWR_Enable: U7.14(B8) ; port Enc_PWR_Enable
V_Enc: R44.1 ; off-sheet V_Enc
Vio: C27.2 C34.2 J6.6 R45.2 R49.1 R50.1 U5.1(VCCA) U7.1(VCCA) ; off-sheet Vio
Vrs485: C28.1 C30.2 C35.1 C36.2 R34.1 R35.2 R39.1 R53.1 U5.23(VCCB) U5.24(VCCB) U6.1(VCC) U7.23(VCCB) U7.24(VCCB) U8.1(VCC) ; off-sheet Vrs485
NetC29_2: C29.2 D5.1 J4.7 J22.5 R33.2 R36.2
NetC31_1: C31.1 D5.2 J4.8 J22.6 R36.1 R37.2
NetC32_2: C32.2 D6.2 J4.2 J22.8 R41.2
NetC33_1: C33.1 D6.1 J4.3 J22.7 R42.2
NetC37_2: C37.2 D7.2 J4.9 J22.4 R52.2
NetC38_1: C38.1 D7.1 J4.5 J22.3 R54.2
NetJ3_2: J3.2 R40.1
NetJ3_6: J3.6 R50.2 U7.3(A1)
NetJ3_8: J3.8 R49.2 U7.4(A2)
NetJ4_1: J4.1 R43.2 TP5.1
NetJ4_4: J4.4 J22.1 R43.1 R44.2
NetJ6_2: J6.2 U5.3(A1)
NetJ6_4: J6.4 R55.2 U7.10(A8)
NetJ6_8: J6.8 U5.4(A2)
NetR31_2: R31.2 U5.2(DIR)
NetR32_1: R32.1 U5.22(~{OE})
NetR33_1: R33.1 U6.8(A)
NetR37_1: R37.1 U6.7(B)
NetR38_2: R38.2 U5.15(B7) U5.16(B6) U5.17(B5) U5.18(B4) U5.19(B3)
NetR39_2: R39.2 R47.2 U6.3(D)
NetR40_2: R40.2 U5.10(A8)
NetR41_1: R41.1 U6.5(Y)
NetR42_1: R42.1 U6.6(Z)
NetR45_1: R45.1 U7.2(DIR)
NetR46_2: R46.2 U7.22(~{OE})
NetR47_1: R47.1 U7.20(B2)
NetR48_1: R48.1 U7.21(B1)
NetR48_2: R48.2 R53.2 U8.3(D)
NetR51_1: R51.1 U7.5(A3) U7.6(A4) U7.7(A5) U7.8(A6) U7.9(A7)
NetR52_1: R52.1 U8.5(Y)
NetR54_1: R54.1 U8.6(Z)
NetR58_1: R58.1 U5.14(B8)
NetR58_2: R58.2 U6.2(R)

Not connected (* = marked no-connect by the designer): J3 4 10; J4 10(MH1) 11(MH2); U5 5(A3) 6(A4) 7(A5) 8(A6) 9(A7); U7 15(B7) 16(B6) 17(B5) 18(B4) 19(B3); U8 2(R) 7(B)* 8(A)*

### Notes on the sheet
- SL
- MA
- RX_SL
- TX_MA
- TX_MO
- (near J6) Vio
- Enc_PWR_Fault
- Enc_PWR_Enable
- (near J6) Enc_PWR_Good
- MO

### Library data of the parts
C27 C28 C30 C34-C36 = 06033D104KAT2A: CAP, CERM, 0.1uF, 25V, +/-10%, X5R, 0603; Manufacturer: AVX; Polarized: N; CompType: Capacitor; U/M: EA; Cap_F: 0.0000001; Tolerance_%: 10; ESR_Ohm: 0.048; Value1: 0.048 ohm; VDC_V: 25; IRMS_A: 0.53; TaMin_C: -55; TaMax_C: 85
C29 C31-C33 C37 C38 = GRM188R71H221KA01D: CAP, CERM, 220pF, 50V, +/-10%, X7R, 0603; Manufacturer: MuRata; Polarized: N; CompType: Capacitor; U/M: EA; Cap_F: 0.00000000022; Tolerance_%: 10; Value1: Unknown; VDC_V: 50; TaMin_C: -55; TaMax_C: 125
D5-D7 = CDSOT23-SM712: Diode, TVS, Bi, 7V, 400W, SOT-23; Manufacturer: Bourns; SymbolCreator: a0411947; U/M: EA; Power_W: 400; Vr_V: 7
J3 = PEC05DAAN: Header, 100mil, 5x2, Tin plated, TH; Manufacturer: Sullins Connector Solutions; SymbolCreator: a0412235; U/M: EA
J4 = 1734348-1: Conn D-SUB RCPT R/A 9POS GOLD/FL, TH; Manufacturer: TE Connectivity; SymbolCreator: a0412235; CompType: Connector; U/M: EA
J6 = PEC04DAAN: Header, 100mil, 4x2, Tin plated, TH; Manufacturer: Sullins Connector Solutions; SymbolCreator: a0411947; U/M: EA
J22 = PEC08SAAN: Header, 8x1, 100mil, Tin, TH; Manufacturer: Sullins Connector Solutions; SymbolCreator: a0411947; U/M: EA
J40 J41 = PEC02SAAN: Header, 100mil, 2x1, Tin plated, TH; Manufacturer: Sullins Connector Solutions; SymbolCreator: a0412235; U/M: EA
R31 R32 R34 R35 R38 R39 R45 R46 R49-R51 R53 R55 = CRCW06034K70JNEA: as R14 on sheet TIDA-00175_revE1_PS
R33 R37 R41 R42 R52 R54 = CRCW060310R0JNEAHP: as R10 on sheet TIDA-00175_revE1_PS
R36 = ERJ-P06J121V: RES, 120 ohm, 5%, 0.5W, 0805; Manufacturer: Panasonic; CompType: Resistor; Value_Code: 120R; Tolerance_%: 5; Power_W: 0.5; VDC_V: 400; TempCo: 200 ppm/C; EIA_Code: E24; U/M: EA
R40 R47 R48 R58 = CRCW060322R0JNEA: RES, 22 ohm, 5%, 0.1W, 0603; Manufacturer: Vishay-Dale; CompType: Resistor; Value_Code: 22R0; Tolerance_%: 5; Power_W: 0.1; VDC_V: 75; TempCo: 200 ppm/C; EIA_Code: E24; U/M: EA
R43 R44 = CRCW06030000Z0EA: as R11 on sheet TIDA-00175_revE1_PS
TP5 = 5000: as TP1 on sheet TIDA-00175_revE1_PS
U5 U7 = SN74AVC8T245PW: 8-BIT DUAL-SUPPLY BUS TRANSCEIVER WITH CONFIGURABLE VOLTAGE TRANSLATION AND 3-STATE OUTPUTS, PW0024A; Alternate Manufacturer: None; Manufacturer: Texas Instruments; SymbolCreator: a0411947; CompType: IC; U/M: EA
U6 U8 = SN65HVD77D: 3.3-V Full-Duplex RS-485 Transceivers With ±12-kV IEC ESD, D0008A; Alternate Manufacturer: None; Manufacturer: Texas Instruments; SymbolCreator: a0799628; CompType: IC; U/M: EA

## Sheet TIDA-00175_revE1_Block_Diagram.SchDoc
size 431 x 279 mm; Date: Not shown in title block; ApprovedBy: Not shown in title block; CheckedBy: Not shown in title block; Author: Not shown in title block; CompanyName: Not shown in title block; Engineer: Not shown in title block; Organization: Not shown in title block; Address1: Not shown in title block; Address2: Not shown in title block; Address3: Not shown in title block; Address4: Not shown in title block; DocumentNumber: 1; Revision: Use project parameter SCH_Rev; SheetNumber: 1; SheetTotal: 4; PageSetup: Record=PageOptions|CenterHorizontal=True|CenterVertical=True|PrintScale=1.00|XCorrection=1.00|YCorrection=1.00|PrintKind=0|BorderSize=5000000|LeftOffset=0|BottomOffset=0|Orientation=2|PaperLength=1000|PaperWidth=1000|Scale=100|PaperSource=15|PrintQuality=600|MediaType=1|DitherType=10|PaperKind=Letter|PrintScaleMode=1
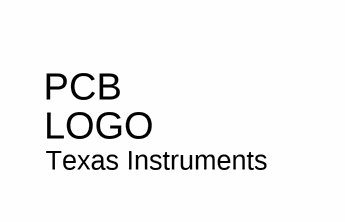
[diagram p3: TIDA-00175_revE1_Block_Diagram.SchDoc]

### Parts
Logo1  Texas Instruments  [TI_Stacked_Overlay_Small]  (no BOM)

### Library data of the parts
Logo1 = TI_Logo: Texas Instrument Corporate Signature; SymbolCreator: a0412235

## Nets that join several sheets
GND: TIDA-00175_revE1_PR (12 pins), TIDA-00175_revE1_PS (34 pins), TIDA-00175_revE1_SC (44 pins)
Enc_OC_Fault: TIDA-00175_revE1_PR (U1.30), TIDA-00175_revE1_SC (R34.2 U5.21)
Enc_PG: TIDA-00175_revE1_PR (U1.31), TIDA-00175_revE1_SC (R35.1 U5.20)
Enc_PWR_Enable: TIDA-00175_revE1_PS (R14.1 U2.3), TIDA-00175_revE1_SC (U7.14)
V_Enc: TIDA-00175_revE1_PR (17 pins), TIDA-00175_revE1_SC (R44.1)
Vio: TIDA-00175_revE1_PS (J2.2), TIDA-00175_revE1_SC (8 pins)
Vout_5V: TIDA-00175_revE1_PR (R1.2 R2.2 R7.2 U1.29), TIDA-00175_revE1_PS (R11.2)
Vrs485: TIDA-00175_revE1_PS (7 pins), TIDA-00175_revE1_SC (14 pins)

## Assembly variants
TIDA-00175_revE1-Complete: all parts fitted
TIDA-00175_revE1: not fitted C4 C10 C12 C19 D3 D4 D5 D6 D7 J40 J41 R4 R6 R43 R44 TP3 TP5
